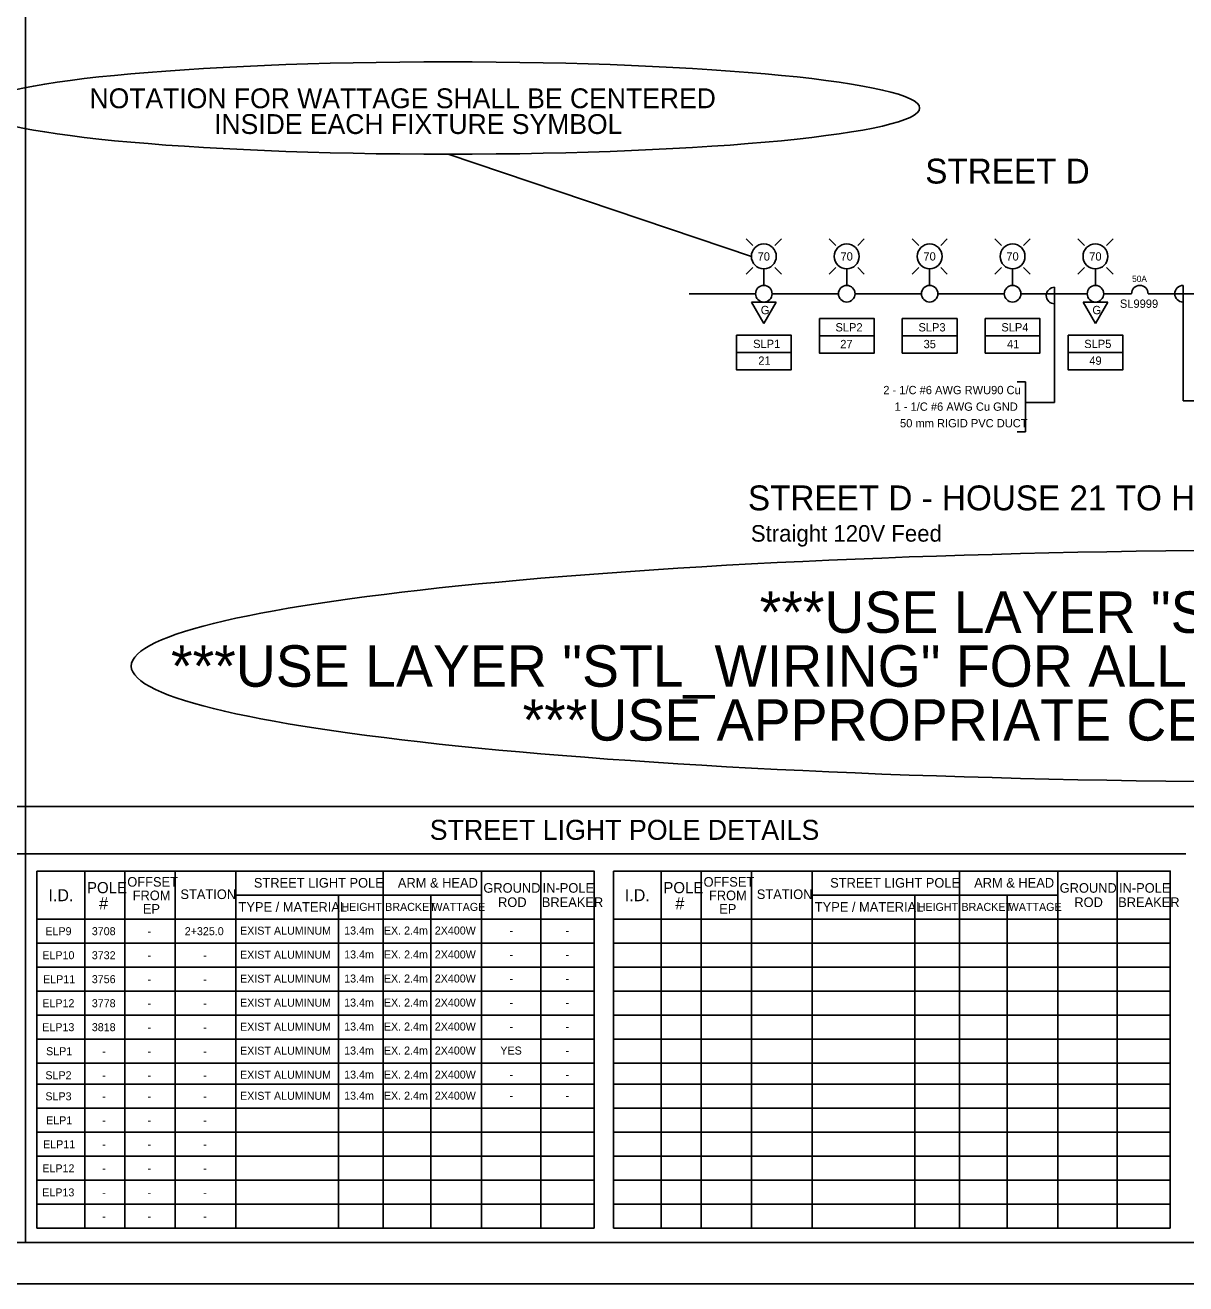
# Model space of a CAD drawing. Extents: x 602909 to 603631, y 4846273 to 4846729.
# Drawn here: x 603054.8 to 603194.8, y 4846352.6 to 4846504.5 of the extents above; entities that cross this region are included whole.
import ezdxf

# ---------------------------------------------------------------- set-up
doc = ezdxf.new("R2010")
doc.units = 0
for name, color, linetype in [('-PRINT HALFSIZE', 7, 'Continuous'), ('ENG_BORDER', 7, 'Continuous'), ('ENG_TITLEBLOCK', 7, 'Continuous'), ('ENG_TX_TITLEBLOCK', 7, 'Continuous'), ('SL - Border Text', 7, 'Continuous'), ('SL - Wiring Diagram - Level 430', 7, 'Continuous'), ('STL_FIXTURES', 7, 'Continuous'), ('STL_GND_PLATE', 7, 'Continuous'), ('STL_ID', 7, 'Continuous'), ('STL_POLES', 7, 'Continuous'), ('STL_POWER_SUPPLY', 7, 'Continuous'), ('STL_WIRING', 7, 'Continuous')]:
    doc.layers.add(name, color=color, linetype=linetype)

msp = doc.modelspace()

# ---------------------------------------------------------------- linework, layer by layer
at = {"layer": '-PRINT HALFSIZE'}
msp.add_lwpolyline([(602959.8, 4846631.64), (603368.72, 4846631.64), (603368.72, 4846352.64), (602959.8, 4846352.64)], close=True, dxfattribs=at)
at = {"layer": 'ENG_BORDER'}
for p, q in [((603054.8, 4846357.64), (603054.8, 4846626.86)), ((602977.52, 4846410.23), (603363.74, 4846410.23)), ((602977.52, 4846404.5), (603194.76, 4846404.5)), ((603363.72, 4846357.64), (602977.52, 4846357.64))]:
    msp.add_line(p, q, dxfattribs=at)
msp.add_lwpolyline([(602977.52, 4846357.64), (603363.72, 4846357.64), (603363.72, 4846626.64), (602977.52, 4846626.64)], close=True, dxfattribs=at)
at = {"layer": 'ENG_TITLEBLOCK'}
for p, q in [((603056.19, 4846402.44), (603056.19, 4846359.34)), ((603061.96, 4846402.44), (603061.96, 4846359.34)), ((603061.96, 4846402.44), (603061.96, 4846396.64)), ((603066.79, 4846402.44), (603066.79, 4846359.34)), ((603080.19, 4846402.44), (603080.19, 4846359.34)), ((603097.96, 4846402.44), (603097.96, 4846359.34)), ((603109.8, 4846402.44), (603109.8, 4846359.34)), ((603116.97, 4846402.44), (603116.97, 4846359.34)), ((603123.38, 4846402.44), (603123.38, 4846359.34)), ((603125.71, 4846402.44), (603125.71, 4846359.34)), ((603131.47, 4846402.44), (603131.47, 4846359.34)), ((603131.47, 4846402.44), (603131.47, 4846396.64)), ((603136.31, 4846402.44), (603136.31, 4846359.34)), ((603149.7, 4846402.44), (603149.7, 4846359.34)), ((603167.48, 4846402.44), (603167.48, 4846359.34)), ((603179.31, 4846402.44), (603179.31, 4846359.34)), ((603186.49, 4846402.44), (603186.49, 4846359.34)), ((603192.89, 4846402.44), (603192.89, 4846359.34)), ((603080.19, 4846399.54), (603109.8, 4846399.54)), ((603092.57, 4846399.54), (603092.57, 4846359.34)), ((603103.7, 4846399.54), (603103.7, 4846359.34)), ((603103.7, 4846396.64), (603103.7, 4846399.54)), ((603149.7, 4846399.54), (603179.31, 4846399.54)), ((603162.09, 4846399.54), (603162.09, 4846359.34)), ((603173.22, 4846399.54), (603173.22, 4846359.34)), ((603173.22, 4846396.64), (603173.22, 4846399.54)), ((603123.38, 4846393.75), (603056.19, 4846393.75)), ((603192.89, 4846393.75), (603125.71, 4846393.75)), ((603123.38, 4846390.85), (603056.19, 4846390.85)), ((603192.89, 4846390.85), (603125.71, 4846390.85)), ((603123.38, 4846387.95), (603056.19, 4846387.95)), ((603192.89, 4846387.95), (603125.71, 4846387.95)), ((603123.38, 4846385.06), (603056.19, 4846385.06)), ((603192.89, 4846385.06), (603125.71, 4846385.06)), ((603123.38, 4846382.16), (603056.19, 4846382.16)), ((603192.89, 4846382.16), (603125.71, 4846382.16)), ((603116.81, 4846379.26), (603056.19, 4846379.26)), ((603123.38, 4846379.26), (603100.06, 4846379.26)), ((603192.89, 4846379.26), (603125.72, 4846379.26)), ((603123.38, 4846376.72), (603056.19, 4846376.72)), ((603192.89, 4846376.72), (603125.71, 4846376.72)), ((603123.38, 4846373.82), (603056.19, 4846373.83)), ((603192.89, 4846373.82), (603125.71, 4846373.83)), ((603123.38, 4846370.93), (603056.19, 4846370.93)), ((603192.89, 4846370.93), (603125.71, 4846370.93)), ((603123.38, 4846368.03), (603056.19, 4846368.03)), ((603192.89, 4846368.03), (603125.71, 4846368.03)), ((603123.38, 4846365.14), (603056.19, 4846365.14)), ((603192.89, 4846365.14), (603125.71, 4846365.14)), ((603123.38, 4846362.24), (603056.19, 4846362.24)), ((603192.89, 4846362.24), (603125.71, 4846362.24)), ((603123.38, 4846359.34), (603056.19, 4846359.34)), ((603192.89, 4846359.34), (603125.71, 4846359.34))]:
    msp.add_line(p, q, dxfattribs=at)
for points in [[(603056.19, 4846402.44), (603123.38, 4846402.44), (603123.38, 4846396.64), (603056.19, 4846396.64)], [(603125.71, 4846402.44), (603192.89, 4846402.44), (603192.89, 4846396.64), (603125.71, 4846396.64)]]:
    msp.add_lwpolyline(points, close=True, dxfattribs=at)
at = {"layer": 'SL - Border Text'}
for p, q in [((603056.19, 4846402.44), (603123.38, 4846402.44)), ((603072.86, 4846402.44), (603072.86, 4846359.34)), ((603109.8, 4846402.44), (603109.8, 4846396.64)), ((603116.97, 4846402.44), (603116.97, 4846396.64)), ((603125.71, 4846402.44), (603192.89, 4846402.44)), ((603142.37, 4846402.44), (603142.37, 4846359.34)), ((603179.31, 4846402.44), (603179.31, 4846396.64)), ((603186.49, 4846402.44), (603186.49, 4846396.64)), ((603123.38, 4846396.64), (603056.19, 4846396.64)), ((603192.89, 4846396.64), (603125.71, 4846396.64))]:
    msp.add_line(p, q, dxfattribs=at)
at = {"layer": 'SL - Wiring Diagram - Level 430'}
for p, q in [((603134.86, 4846472.08), (603142.86, 4846472.08)), ((603144.86, 4846472.08), (603152.86, 4846472.08)), ((603154.86, 4846472.08), (603162.86, 4846472.08)), ((603164.86, 4846472.08), (603172.86, 4846472.08)), ((603174.86, 4846472.08), (603182.86, 4846472.08)), ((603188.21, 4846472.08), (603184.86, 4846472.08)), ((603184.86, 4846472.08), (603188.21, 4846472.08)), ((603190.35, 4846472.08), (603198.35, 4846472.08))]:
    msp.add_line(p, q, dxfattribs=at)
for points in [[(603134.86, 4846472.08), (603142.86, 4846472.08)], [(603144.86, 4846472.08), (603152.86, 4846472.08)], [(603162.86, 4846472.08), (603154.86, 4846472.08)], [(603172.86, 4846472.08), (603164.86, 4846472.08)], [(603174.86, 4846472.08), (603182.86, 4846472.08)], [(603190.35, 4846472.08), (603198.35, 4846472.08)]]:
    msp.add_lwpolyline(points, dxfattribs=at)
at = {"layer": 'STL_FIXTURES'}
for p, q in [((603142.54, 4846477.9), (603141.74, 4846478.7)), ((603145.19, 4846477.9), (603145.98, 4846478.7)), ((603152.54, 4846477.9), (603151.74, 4846478.7)), ((603155.19, 4846477.9), (603155.98, 4846478.7)), ((603162.54, 4846477.9), (603161.74, 4846478.7)), ((603165.19, 4846477.9), (603165.98, 4846478.7)), ((603172.54, 4846477.9), (603171.74, 4846478.7)), ((603175.19, 4846477.9), (603175.98, 4846478.7)), ((603182.54, 4846477.9), (603181.74, 4846478.7)), ((603185.19, 4846477.9), (603185.98, 4846478.7)), ((603142.54, 4846475.25), (603141.74, 4846474.45)), ((603143.86, 4846475.08), (603143.86, 4846473.08)), ((603145.19, 4846475.25), (603145.98, 4846474.45)), ((603152.54, 4846475.25), (603151.74, 4846474.45)), ((603153.86, 4846475.08), (603153.86, 4846473.08)), ((603155.19, 4846475.25), (603155.98, 4846474.45)), ((603162.54, 4846475.25), (603161.74, 4846474.45)), ((603163.86, 4846475.08), (603163.86, 4846473.08)), ((603165.19, 4846475.25), (603165.98, 4846474.45)), ((603172.54, 4846475.25), (603171.74, 4846474.45)), ((603173.86, 4846475.08), (603173.86, 4846473.08)), ((603175.19, 4846475.25), (603175.98, 4846474.45)), ((603182.54, 4846475.25), (603181.74, 4846474.45)), ((603183.86, 4846475.08), (603183.86, 4846473.08)), ((603185.19, 4846475.25), (603185.98, 4846474.45))]:
    msp.add_line(p, q, dxfattribs=at)
for centre, radius in [((603143.86, 4846476.58), 1.5), ((603153.86, 4846476.58), 1.5), ((603163.86, 4846476.58), 1.5), ((603173.86, 4846476.58), 1.5), ((603183.86, 4846476.58), 1.5), ((603153.86, 4846472.08), 1)]:
    msp.add_circle(centre, radius, dxfattribs=at)
at = {"layer": 'STL_GND_PLATE'}
for p, q in [((603143.86, 4846468.48), (603142.36, 4846471.08)), ((603142.36, 4846471.08), (603145.36, 4846471.08)), ((603145.36, 4846471.08), (603143.86, 4846468.48)), ((603183.86, 4846468.48), (603182.36, 4846471.08)), ((603182.36, 4846471.08), (603185.36, 4846471.08)), ((603185.36, 4846471.08), (603183.86, 4846468.48))]:
    msp.add_line(p, q, dxfattribs=at)
at = {"layer": 'STL_ID'}
for p, q in [((603105.77, 4846488.91), (603142.36, 4846476.58)), ((603150.56, 4846466.99), (603157.17, 4846466.99)), ((603160.56, 4846466.99), (603167.17, 4846466.99)), ((603170.56, 4846466.99), (603177.17, 4846466.99)), ((603140.56, 4846464.99), (603147.17, 4846464.99)), ((603180.56, 4846464.99), (603187.17, 4846464.99))]:
    msp.add_line(p, q, dxfattribs=at)
for points in [[(603150.56, 4846469.08), (603157.17, 4846469.08), (603157.17, 4846464.91), (603150.56, 4846464.91)], [(603160.56, 4846469.08), (603167.17, 4846469.08), (603167.17, 4846464.91), (603160.56, 4846464.91)], [(603170.56, 4846469.08), (603177.17, 4846469.08), (603177.17, 4846464.91), (603170.56, 4846464.91)], [(603140.56, 4846467.08), (603147.17, 4846467.08), (603147.17, 4846462.91), (603140.56, 4846462.91)], [(603180.56, 4846467.08), (603187.17, 4846467.08), (603187.17, 4846462.91), (603180.56, 4846462.91)]]:
    msp.add_lwpolyline(points, close=True, dxfattribs=at)
for centre, major_axis in [((603105.77, 4846494.48), (56.88, 0)), ((603210.54, 4846427.17), (142.98, 0))]:
    msp.add_ellipse(centre, major_axis=major_axis, ratio=0.097916, dxfattribs=at)
at = {"layer": 'STL_POLES'}
for centre in [(603143.86, 4846472.08), (603153.86, 4846472.08), (603163.86, 4846472.08), (603173.86, 4846472.08), (603183.86, 4846472.08)]:
    msp.add_circle(centre, 1, dxfattribs=at)
at = {"layer": 'STL_POWER_SUPPLY'}
for p, q in [((603188.21, 4846472.08), (603187.21, 4846472.08)), ((603190.21, 4846472.08), (603191.21, 4846472.08))]:
    msp.add_line(p, q, dxfattribs=at)
msp.add_arc((603189.21, 4846472.08), 1, 0, 180, dxfattribs=at)
at = {"layer": 'STL_WIRING'}
for p, q in [((603178.93, 4846472.86), (603178.93, 4846470.86)), ((603194.43, 4846473.08), (603194.43, 4846471.08)), ((603152.86, 4846472.08), (603144.86, 4846472.08)), ((603162.86, 4846472.08), (603154.86, 4846472.08)), ((603172.86, 4846472.08), (603164.86, 4846472.08)), ((603182.86, 4846472.08), (603174.86, 4846472.08)), ((603188.21, 4846472.08), (603184.86, 4846472.08)), ((603190.21, 4846472.08), (603200.58, 4846472.08)), ((603178.93, 4846470.86), (603178.93, 4846458.94)), ((603194.43, 4846471.08), (603194.43, 4846459.15)), ((603174.43, 4846461.46), (603175.43, 4846461.46)), ((603194.43, 4846459.15), (603197.81, 4846459.15)), ((603175.43, 4846458.94), (603178.93, 4846458.94)), ((603174.43, 4846455.42), (603175.43, 4846455.42))]:
    msp.add_line(p, q, dxfattribs=at)
msp.add_lwpolyline([(603175.43, 4846455.42), (603175.43, 4846461.46)], dxfattribs=at)
for centre in [(603178.93, 4846471.86), (603194.43, 4846472.08)]:
    msp.add_arc(centre, 1, 90, 270, dxfattribs=at)

# ---------------------------------------------------------------- texts
at = {"layer": 'ENG_TX_TITLEBLOCK'}
for s, height, p in [('NOTATION FOR WATTAGE SHALL BE CENTERED ', 2.3927, (603062.52, 4846494.46)), ('INSIDE EACH FIXTURE SYMBOL', 2.3927, (603077.55, 4846491.35)), ('STREET D', 3, (603163.33, 4846485.37)), ('STREET D - HOUSE 21 TO HOUSE 49', 3, (603141.94, 4846445.95)), ('Straight 120V Feed', 2, (603142.29, 4846442.17)), ('***USE LAYER "STL_ID" ALL TEXT***', 5, (603143.36, 4846431.17)), ('***USE LAYER "STL_WIRING" FOR ALL LINE DIAGRAM CONNECTIONS***', 5, (603072.36, 4846424.67)), ('***USE APPROPRIATE CELLS AS PER LEGEND ***', 5, (603114.76, 4846418.17))]:
    msp.add_text(s, height=height, dxfattribs=at).set_placement(p)
for s, height, rotation, p in [('STREET LIGHT POLE DETAILS', 2.4137, 360, (603103.56, 4846406.2)), ('OFFSET', 1.159, 359.9999, (603067.08, 4846400.55)), ('STREET LIGHT POLE', 1.1586, 359.9999, (603082.35, 4846400.44)), ('ARM & HEAD', 1.159, 359.9999, (603099.72, 4846400.44)), ('OFFSET', 1.159, 359.9999, (603136.59, 4846400.55)), ('STREET LIGHT POLE', 1.1586, 359.9999, (603151.86, 4846400.44)), ('ARM & HEAD', 1.159, 359.9999, (603169.23, 4846400.44)), ('I.D.', 1.448, 359.9999, (603057.57, 4846398.8)), ('POLE', 1.352, 359.9999, (603062.22, 4846399.76)), ('FROM', 1.159, 359.9999, (603067.73, 4846398.92)), ('STATION', 1.159, 359.9999, (603073.49, 4846399.06)), ('GROUND', 1.159, 359.9999, (603110.03, 4846399.82)), ('IN-POLE', 1.159, 359.9999, (603117.18, 4846399.82)), ('I.D.', 1.448, 359.9999, (603127.09, 4846398.8)), ('POLE', 1.352, 359.9999, (603131.74, 4846399.76)), ('FROM', 1.159, 359.9999, (603137.24, 4846398.92)), ('STATION', 1.159, 359.9999, (603143.01, 4846399.06)), ('GROUND', 1.159, 359.9999, (603179.54, 4846399.82)), ('IN-POLE', 1.159, 359.9999, (603186.7, 4846399.82)), ('#', 1.45, 359.9999, (603063.68, 4846397.81)), ('EP', 1.159, 359.9999, (603068.96, 4846397.29)), ('TYPE / MATERIAL', 1.1586, 359.9999, (603080.5, 4846397.53)), ('HEIGHT', 0.965, 359.9999, (603092.91, 4846397.63)), ('BRACKET', 0.965, 359.9999, (603098.19, 4846397.63)), ('WATTAGE', 0.965, 359.9999, (603103.88, 4846397.63)), ('ROD', 1.159, 359.9999, (603111.8, 4846398.1)), ('BREAKER', 1.159, 359.9999, (603117.08, 4846398.1)), ('#', 1.45, 359.9999, (603133.19, 4846397.81)), ('EP', 1.159, 359.9999, (603138.48, 4846397.29)), ('TYPE / MATERIAL', 1.1586, 359.9999, (603150.01, 4846397.53)), ('HEIGHT', 0.965, 359.9999, (603162.42, 4846397.63)), ('BRACKET', 0.965, 359.9999, (603167.7, 4846397.63)), ('WATTAGE', 0.965, 359.9999, (603173.4, 4846397.63)), ('ROD', 1.159, 359.9999, (603181.31, 4846398.1)), ('BREAKER', 1.159, 359.9999, (603186.6, 4846398.1)), ('ELP9', 0.965, 359.9999, (603057.2, 4846394.7)), ('3708', 0.965, 359.9999, (603062.8, 4846394.7)), ('2+325.0', 0.965, 359.9999, (603074.01, 4846394.7)), ('EXIST ALUMINUM', 0.9655, 359.9999, (603080.68, 4846394.76)), ('13.4m', 0.965, 359.9999, (603093.24, 4846394.78)), ('EX. 2.4m', 0.965, 359.9999, (603098.03, 4846394.78)), ('2X400W', 0.965, 359.9999, (603104.17, 4846394.78)), ('-', 0.965, 359.9999, (603113.19, 4846394.78)), ('-', 0.965, 359.9999, (603119.95, 4846394.78)), ('-', 0.965, 359.9999, (603069.52, 4846394.7)), ('ELP10', 0.965, 359.9999, (603056.83, 4846391.8)), ('3732', 0.965, 359.9999, (603062.8, 4846391.8)), ('-', 0.965, 359.9999, (603069.52, 4846391.8)), ('-', 0.965, 359.9999, (603076.23, 4846391.8)), ('EXIST ALUMINUM', 0.9655, 359.9999, (603080.68, 4846391.86)), ('13.4m', 0.965, 359.9999, (603093.24, 4846391.89)), ('EX. 2.4m', 0.965, 359.9999, (603098.03, 4846391.89)), ('2X400W', 0.965, 359.9999, (603104.17, 4846391.89)), ('-', 0.965, 359.9999, (603113.19, 4846391.89)), ('-', 0.965, 359.9999, (603119.95, 4846391.89)), ('ELP11', 0.965, 359.9999, (603056.92, 4846388.91)), ('3756', 0.965, 359.9999, (603062.8, 4846388.91)), ('-', 0.965, 359.9999, (603069.52, 4846388.91)), ('-', 0.965, 359.9999, (603076.23, 4846388.91)), ('EXIST ALUMINUM', 0.9655, 359.9999, (603080.68, 4846388.97)), ('13.4m', 0.965, 359.9999, (603093.24, 4846388.99)), ('EX. 2.4m', 0.965, 359.9999, (603098.03, 4846388.99)), ('2X400W', 0.965, 359.9999, (603104.17, 4846388.99)), ('-', 0.965, 359.9999, (603113.19, 4846388.99)), ('-', 0.965, 359.9999, (603119.95, 4846388.99)), ('ELP12', 0.965, 359.9999, (603056.83, 4846386.01)), ('3778', 0.965, 359.9999, (603062.8, 4846386.01)), ('-', 0.965, 359.9999, (603069.52, 4846386.01)), ('-', 0.965, 359.9999, (603076.23, 4846386.01)), ('EXIST ALUMINUM', 0.9655, 359.9999, (603080.68, 4846386.07)), ('13.4m', 0.965, 359.9999, (603093.24, 4846386.09)), ('EX. 2.4m', 0.965, 359.9999, (603098.03, 4846386.09)), ('2X400W', 0.965, 359.9999, (603104.17, 4846386.09)), ('-', 0.965, 359.9999, (603113.19, 4846386.09)), ('-', 0.965, 359.9999, (603119.95, 4846386.09)), ('ELP13', 0.965, 359.9999, (603056.82, 4846383.12)), ('3818', 0.965, 359.9999, (603062.8, 4846383.12)), ('-', 0.965, 359.9999, (603069.52, 4846383.12)), ('-', 0.965, 359.9999, (603076.23, 4846383.12)), ('EXIST ALUMINUM', 0.9655, 359.9999, (603080.68, 4846383.17)), ('13.4m', 0.965, 359.9999, (603093.24, 4846383.2)), ('EX. 2.4m', 0.965, 359.9999, (603098.03, 4846383.2)), ('2X400W', 0.965, 359.9999, (603104.17, 4846383.2)), ('-', 0.965, 359.9999, (603113.19, 4846383.2)), ('-', 0.965, 359.9999, (603119.95, 4846383.2)), ('SLP1', 0.965, 359.9999, (603057.29, 4846380.22)), ('-', 0.965, 359.9999, (603064.06, 4846380.22)), ('-', 0.965, 359.9999, (603069.52, 4846380.22)), ('-', 0.965, 359.9999, (603076.23, 4846380.22)), ('EXIST ALUMINUM', 0.9655, 359.9999, (603080.68, 4846380.28)), ('13.4m', 0.965, 359.9999, (603093.24, 4846380.3)), ('EX. 2.4m', 0.965, 359.9999, (603098.03, 4846380.3)), ('2X400W', 0.965, 359.9999, (603104.17, 4846380.3)), ('YES', 0.965, 359.9999, (603112.08, 4846380.3)), ('-', 0.965, 359.9999, (603119.95, 4846380.3)), ('SLP2', 0.965, 359.9999, (603057.2, 4846377.32)), ('-', 0.965, 359.9999, (603064.06, 4846377.32)), ('-', 0.965, 359.9999, (603069.52, 4846377.32)), ('-', 0.965, 359.9999, (603076.23, 4846377.32)), ('EXIST ALUMINUM', 0.9655, 359.9999, (603080.68, 4846377.38)), ('13.4m', 0.965, 359.9999, (603093.24, 4846377.4)), ('EX. 2.4m', 0.965, 359.9999, (603098.03, 4846377.4)), ('2X400W', 0.965, 359.9999, (603104.17, 4846377.4)), ('-', 0.965, 359.9999, (603113.19, 4846377.4)), ('-', 0.965, 359.9999, (603119.95, 4846377.4)), ('SLP3', 0.965, 359.9999, (603057.2, 4846374.78)), ('EXIST ALUMINUM', 0.9655, 359.9999, (603080.68, 4846374.84)), ('13.4m', 0.965, 359.9999, (603093.24, 4846374.86)), ('EX. 2.4m', 0.965, 359.9999, (603098.03, 4846374.86)), ('2X400W', 0.965, 359.9999, (603104.17, 4846374.86)), ('-', 0.965, 359.9999, (603064.06, 4846374.78)), ('-', 0.965, 359.9999, (603069.52, 4846374.78)), ('-', 0.965, 359.9999, (603076.23, 4846374.78)), ('-', 0.965, 359.9999, (603113.19, 4846374.86)), ('-', 0.965, 359.9999, (603119.95, 4846374.86)), ('ELP1', 0.965, 359.9999, (603057.29, 4846371.88)), ('-', 0.965, 359.9999, (603064.06, 4846371.88)), ('-', 0.965, 359.9999, (603069.52, 4846371.88)), ('-', 0.965, 359.9999, (603076.23, 4846371.88)), ('ELP11', 0.965, 359.9999, (603056.92, 4846368.99)), ('-', 0.965, 359.9999, (603064.06, 4846368.99)), ('-', 0.965, 359.9999, (603069.52, 4846368.99)), ('-', 0.965, 359.9999, (603076.23, 4846368.99)), ('ELP12', 0.965, 359.9999, (603056.83, 4846366.09)), ('-', 0.965, 359.9999, (603064.06, 4846366.09)), ('-', 0.965, 359.9999, (603069.52, 4846366.09)), ('-', 0.965, 359.9999, (603076.23, 4846366.09)), ('ELP13', 0.965, 359.9999, (603056.82, 4846363.19)), ('-', 0.965, 359.9999, (603064.06, 4846363.19)), ('-', 0.965, 359.9999, (603069.52, 4846363.19)), ('-', 0.965, 359.9999, (603076.23, 4846363.19)), ('-', 0.965, 359.9999, (603064.06, 4846360.3)), ('-', 0.965, 359.9999, (603069.52, 4846360.3)), ('-', 0.965, 359.9999, (603076.23, 4846360.3))]:
    msp.add_text(s, height=height, rotation=rotation, dxfattribs=at).set_placement(p)
at = {"layer": 'STL_GND_PLATE'}
for p in [(603143.49, 4846469.61), (603183.49, 4846469.61)]:
    msp.add_text('G', height=1, rotation=359.9999, dxfattribs=at).set_placement(p)
at = {"layer": 'STL_ID'}
for s, p in [('70', (603143.11, 4846476.08)), ('70', (603153.11, 4846476.08)), ('70', (603163.11, 4846476.08)), ('70', (603173.11, 4846476.08)), ('70', (603183.11, 4846476.08)), ('SLP2', (603152.5, 4846467.53)), ('SLP3', (603162.51, 4846467.53)), ('SLP4', (603172.51, 4846467.53)), ('SLP1', (603142.57, 4846465.53)), ('27', (603153.08, 4846465.51)), ('35', (603163.13, 4846465.51)), ('41', (603173.19, 4846465.51)), ('SLP5', (603182.51, 4846465.53)), ('21', (603143.19, 4846463.51)), ('49', (603183.12, 4846463.51)), ('2 - 1/C #6 AWG RWU90 Cu', (603158.27, 4846459.96)), ('1 - 1/C #6 AWG Cu GND', (603159.63, 4846457.96)), ('50 mm RIGID PVC DUCT', (603160.29, 4846455.96))]:
    msp.add_text(s, height=1, dxfattribs=at).set_placement(p)
at = {"layer": 'STL_POWER_SUPPLY'}
msp.add_text('50A', height=0.75, dxfattribs=at).set_placement((603188.28, 4846473.5))
msp.add_text('SL9999', height=1, rotation=359.9999, dxfattribs=at).set_placement((603186.81, 4846470.38))

doc.saveas('drawing.dxf')
